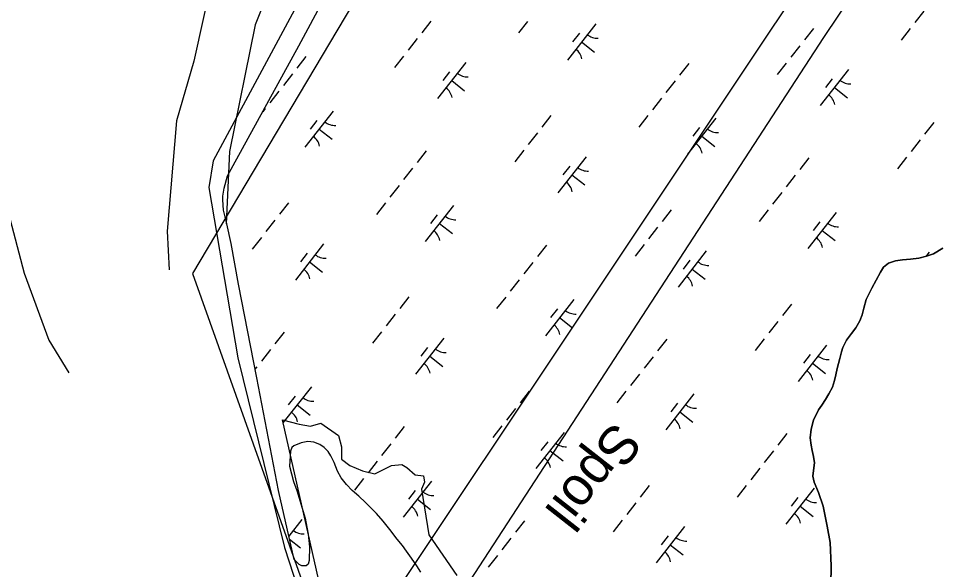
# Model space of a CAD drawing. Extents: x 3896831 to 3918110, y 171006 to 193349.
# Drawn here: x 3907802 to 3908805, y 177519 to 178119 of the extents above; entities that cross this region are included whole.
import ezdxf

# ---------------------------------------------------------------- set-up
doc = ezdxf.new("R2010")
doc.units = 0
for name, color, linetype in [('V-CHAN-SPOL', 7, 'Continuous'), ('V-RIVR-EDGE', 7, 'Continuous'), ('V-RRAP-FSHR', 7, 'Continuous'), ('V-TOPO-DPTH', 7, 'Continuous'), ('V-TOPO-MINR', 7, 'Continuous'), ('V-TOPO-SHOR', 7, 'Continuous'), ('V-UTIL-LINE', 7, 'Continuous'), ('V-WETL-SWMP', 7, 'Continuous')]:
    doc.layers.add(name, color=color, linetype=linetype)

msp = doc.modelspace()

# ---------------------------------------------------------------- linework, layer by layer
at = {"layer": 'V-RIVR-EDGE'}
for points in [[(3908140.8, 178198.6), (3908014.4, 177963.8), (3908009.9, 177934.5), (3908041.5, 177749.4), (3908092.3, 177542.9), (3908130.7, 177424.4)], [(3908136.3, 177476.3), (3908090.1, 177681.7), (3908108.1, 177677.2), (3908120.5, 177674.9), (3908131.8, 177678.3), (3908151, 177664.8), (3908154.4, 177652.3), (3908154.4, 177638.8), (3908163.4, 177632), (3908177, 177626.4), (3908190.5, 177623), (3908208.6, 177632), (3908219.8, 177633.2), (3908225.5, 177629.8), (3908234.5, 177621.9), (3908243.5, 177620.7), (3908244.7, 177614), (3908241.3, 177606.1), (3908249.2, 177556.4), (3908279.7, 177512.4)]]:
    msp.add_lwpolyline(points, dxfattribs=at)
at = {"layer": 'V-RRAP-FSHR'}
msp.add_lwpolyline([(3910095.3, 181395.6), (3909257.3, 180118.1), (3908889.4, 179541.5), (3908614.7, 178888.4), (3907991.9, 177840.9), (3908307, 176956.6)], dxfattribs=at)
at = {"layer": 'V-TOPO-DPTH'}
msp.add_lwpolyline([(3908187.5, 178582.2), (3908149.5, 178485.1), (3908118.7, 178425.4), (3908061.6, 178286.4), (3908015.2, 178171), (3907993.6, 178072.1), (3907974.6, 178007.1), (3907964.5, 177887.3), (3907966.5, 177845.1)], dxfattribs=at)
at = {"layer": 'V-TOPO-MINR'}
for points in [[(3908537.4, 179043.2), (3908434.2, 178833), (3908266.3, 178537.3), (3908184.5, 178417.7), (3908134.2, 178297.4), (3908060.4, 178111.6), (3908032.4, 177973.8), (3908028.6, 177895.2)], [(3907786.2, 178645.6), (3907752, 178569), (3907730.7, 178485.8), (3907721.7, 178357.1), (3907734.2, 178235.5), (3907783.8, 177937), (3907808.8, 177841.5), (3907835.6, 177768.6), (3907857.3, 177732.9)], [(3908187.5, 178582.2), (3908149.5, 178485.1), (3908118.7, 178425.4), (3908061.6, 178286.4), (3908015.2, 178171), (3907993.6, 178072.1), (3907974.6, 178007.1), (3907964.5, 177887.3), (3907966.5, 177845.1)]]:
    msp.add_lwpolyline(points, dxfattribs=at)
at = {"layer": 'V-TOPO-SHOR'}
for points in [[(3908744.3, 177847.9), (3908749.9, 177852.4), (3908757.3, 177854.8), (3908764.9, 177856), (3908773.8, 177856.5), (3908782.9, 177857.7), (3908791.1, 177859.8), (3908798.6, 177862.6), (3908809, 177868.5)], [(3908687, 177502.1), (3908687.2, 177522.8), (3908686.4, 177548.1), (3908683.1, 177565.9), (3908678.7, 177587.9), (3908673.5, 177602.6), (3908668.9, 177613.9), (3908667.2, 177620.3), (3908668, 177626.6), (3908669.1, 177634.8), (3908668.1, 177641.9), (3908666.5, 177648.5), (3908665.5, 177654.1), (3908664.6, 177662.1), (3908665.6, 177671.6), (3908668.2, 177681.5), (3908673.4, 177692.8), (3908677.1, 177697.7), (3908681.1, 177703.8), (3908684.7, 177710), (3908688.7, 177717.4), (3908691, 177724.7), (3908692.3, 177730.9), (3908693.8, 177737.7), (3908696.6, 177748.6), (3908698.5, 177755.6), (3908700.2, 177760.5), (3908704.2, 177768.5), (3908709.4, 177775.9), (3908714.1, 177781.9), (3908718.5, 177789.5), (3908721.1, 177796.2), (3908723, 177803.2), (3908725.6, 177812.7), (3908731.7, 177825.2), (3908740.9, 177842.6), (3908744.3, 177847.9)]]:
    msp.add_lwpolyline(points, dxfattribs=at)
at = {"layer": 'V-UTIL-LINE'}
for points in [[(3905549.4, 173652.6), (3906763.3, 174938.4), (3906949.5, 175133), (3906970.6, 175166.8), (3907325.9, 175860.5), (3907748.9, 176681), (3908142.2, 177273.2), (3908679.4, 178098), (3908869.7, 178381.4), (3908937.4, 178537.8), (3909170, 179117.3), (3909533.8, 179633.3), (3910092.1, 180424.3), (3910333.2, 180766.9), (3910760.4, 181291.4), (3910921.1, 181524), (3911225.6, 181951.2), (3911822, 182788.6), (3911961.6, 182987.4), (3912147.7, 183114.3), (3912722.9, 183841.8), (3913090.9, 184307.1), (3913848, 185258.8), (3914364, 185910.1)], [(3913133.2, 183520.4), (3913116.3, 183516.1), (3912989.4, 183516.1), (3912744.1, 183393.5), (3911902.4, 182441.8), (3910866.1, 181249.1), (3910603.9, 180953), (3910214.7, 180504.6), (3910138.6, 180390.4), (3909757.9, 179819.4), (3909457.6, 179366.9), (3909009.3, 178685.9), (3908785.1, 178351.7), (3908150.7, 177400.1), (3907770, 176816.4), (3907693.9, 176706.4), (3907647.3, 176630.3), (3907300.5, 175936.6), (3907025.6, 175369.8), (3906945.2, 175204.9), (3906416.5, 174650.8), (3905507.1, 173682.2)]]:
    msp.add_lwpolyline(points, dxfattribs=at)
at = {"layer": 'V-WETL-SWMP'}
for p, q in [((3908107.9, 178089), (3908150.2, 178168)), ((3908788.3, 178126.7), (3908778.4, 178114.1)), ((3908251.4, 178115.6), (3908241.5, 178103)), ((3908356.9, 178115.5), (3908347, 178102.9)), ((3908431, 178112.8), (3908400.1, 178073.4)), ((3908668, 178107.9), (3908658.2, 178095.3)), ((3908773.5, 178107.8), (3908763.6, 178095.2)), ((3908236.6, 178096.7), (3908226.7, 178084.1)), ((3908413.2, 178102.6), (3908405.8, 178093.1)), ((3908030.1, 177947.5), (3908107.9, 178089)), ((3908415.6, 178093.1), (3908429.7, 178082)), ((3908653.2, 178089), (3908643.4, 178076.4)), ((3908115.5, 178077.2), (3908105.7, 178064.7)), ((3908221.8, 178077.8), (3908211.9, 178065.2)), ((3908289.6, 178070.8), (3908258.8, 178031.5)), ((3908532.2, 178069.5), (3908522.3, 178057)), ((3908638.4, 178070.1), (3908628.6, 178057.5)), ((3908100.7, 178058.4), (3908090.9, 178045.8)), ((3908271.8, 178060.6), (3908264.4, 178051.2)), ((3908706.2, 178063.1), (3908675.4, 178023.8)), ((3908274.2, 178051.1), (3908288.3, 178040)), ((3908517.4, 178050.7), (3908507.5, 178038.1)), ((3908688.5, 178052.9), (3908681.1, 178043.5)), ((3908085.9, 178039.5), (3908076.1, 178026.9)), ((3908690.8, 178043.4), (3908705, 178032.3)), ((3908502.6, 178031.8), (3908492.7, 178019.2)), ((3908071.1, 178020.6), (3908068.4, 178017.1)), ((3908145.3, 178017.8), (3908114.4, 177978.5)), ((3908127.5, 178007.7), (3908120.1, 177998.2)), ((3908382.3, 178013), (3908372.4, 178000.4)), ((3908487.8, 178012.9), (3908477.9, 178000.3)), ((3908561.9, 178010.1), (3908531.1, 177970.8)), ((3908799, 178005.3), (3908789.1, 177992.7)), ((3908129.8, 177998.2), (3908144, 177987.1)), ((3908544.1, 178000), (3908536.7, 177990.5)), ((3908367.5, 177994.1), (3908357.6, 177981.5)), ((3908546.5, 177990.5), (3908560.7, 177979.4)), ((3908784.2, 177986.4), (3908774.3, 177973.8)), ((3908352.7, 177975.2), (3908342.8, 177962.6)), ((3908246.5, 177974.6), (3908236.6, 177962)), ((3908420.5, 177968.2), (3908389.7, 177928.8)), ((3908663.1, 177966.9), (3908653.2, 177954.3)), ((3908769.3, 177967.5), (3908759.5, 177954.9)), ((3908231.7, 177955.8), (3908221.8, 177943.2)), ((3908402.7, 177958), (3908395.3, 177948.6)), ((3908026.3, 177934.1), (3908030.1, 177947.5)), ((3908405.1, 177948.5), (3908419.3, 177937.4)), ((3908648.3, 177948.1), (3908638.4, 177935.5)), ((3908216.9, 177936.9), (3908207, 177924.3)), ((3908024.9, 177921.4), (3908025.1, 177925.4)), ((3908025.1, 177925.4), (3908026.3, 177934.1)), ((3908633.5, 177929.2), (3908623.6, 177916.6)), ((3908025.9, 177910.1), (3908024.9, 177921.4)), ((3908096.6, 177918.1), (3908086.7, 177905.5)), ((3908202.1, 177918), (3908192.2, 177905.4)), ((3908276.2, 177915.2), (3908245.3, 177875.9)), ((3908027.5, 177902.9), (3908025.9, 177910.1)), ((3908258.4, 177905), (3908251, 177895.6)), ((3908513.2, 177910.4), (3908503.4, 177897.8)), ((3908618.7, 177910.3), (3908608.8, 177897.7)), ((3908692.8, 177907.5), (3908662, 177868.2)), ((3908029.5, 177895.2), (3908027.5, 177902.9)), ((3908034.1, 177873.7), (3908029.5, 177895.2)), ((3908081.8, 177899.2), (3908071.9, 177886.6)), ((3908260.8, 177895.6), (3908274.9, 177884.5)), ((3908675, 177897.3), (3908667.6, 177887.9)), ((3908498.4, 177891.5), (3908488.6, 177878.9)), ((3908677.4, 177887.9), (3908691.6, 177876.8)), ((3908067, 177880.3), (3908057.1, 177867.7)), ((3908042.1, 177829.4), (3908034.1, 177873.7)), ((3908134.8, 177873.3), (3908104, 177833.9)), ((3908377.4, 177872), (3908367.5, 177859.4)), ((3908483.6, 177872.6), (3908473.8, 177860)), ((3908551.4, 177865.6), (3908520.6, 177826.2)), ((3908809, 177868.5), (3908798.6, 177862.6)), ((3908117, 177863.1), (3908109.6, 177853.6)), ((3908533.6, 177855.4), (3908526.2, 177845.9)), ((3908757.3, 177854.8), (3908749.9, 177852.4)), ((3908764.9, 177856), (3908757.3, 177854.8)), ((3908773.8, 177856.5), (3908764.9, 177856)), ((3908782.9, 177857.7), (3908773.8, 177856.5)), ((3908791.1, 177859.8), (3908782.9, 177857.7)), ((3908794, 177864.3), (3908790.4, 177859.6)), ((3908798.6, 177862.6), (3908791.1, 177859.8)), ((3908119.4, 177853.6), (3908133.5, 177842.5)), ((3908362.6, 177853.1), (3908352.7, 177840.5)), ((3908536, 177845.9), (3908550.2, 177834.8)), ((3908744.3, 177847.9), (3908740.9, 177842.6)), ((3908749.9, 177852.4), (3908744.3, 177847.9)), ((3908740.9, 177842.6), (3908731.7, 177825.2)), ((3908062.1, 177727.5), (3908042.1, 177829.4)), ((3908347.8, 177834.3), (3908337.9, 177821.7)), ((3908731.7, 177825.2), (3908725.6, 177812.7)), ((3908227.5, 177815.5), (3908217.6, 177802.9)), ((3908333, 177815.4), (3908323.1, 177802.8)), ((3908407.1, 177812.6), (3908376.3, 177773.3)), ((3908644.2, 177807.8), (3908634.3, 177795.2)), ((3908725.6, 177812.7), (3908723, 177803.2)), ((3908212.7, 177796.6), (3908202.8, 177784)), ((3908389.3, 177802.4), (3908381.9, 177793)), ((3908721.1, 177796.2), (3908718.5, 177789.5)), ((3908723, 177803.2), (3908721.1, 177796.2)), ((3908391.7, 177793), (3908405.9, 177781.8)), ((3908629.3, 177788.9), (3908619.5, 177776.3)), ((3908718.5, 177789.5), (3908714.1, 177781.9)), ((3908091.7, 177777.1), (3908081.8, 177764.5)), ((3908197.9, 177777.7), (3908188, 177765.1)), ((3908709.4, 177775.9), (3908704.2, 177768.5)), ((3908714.1, 177781.9), (3908709.4, 177775.9)), ((3908265.7, 177770.7), (3908234.9, 177731.3)), ((3908508.3, 177769.4), (3908498.4, 177756.8)), ((3908614.5, 177770), (3908604.7, 177757.4)), ((3908704.2, 177768.5), (3908700.2, 177760.5)), ((3908076.9, 177758.2), (3908067, 177745.6)), ((3908247.9, 177760.5), (3908240.5, 177751)), ((3908682.4, 177763), (3908651.5, 177723.6)), ((3908698.5, 177755.6), (3908696.6, 177748.6)), ((3908700.2, 177760.5), (3908698.5, 177755.6)), ((3908250.3, 177751), (3908264.5, 177739.9)), ((3908493.5, 177750.5), (3908483.6, 177737.9)), ((3908664.6, 177752.8), (3908657.2, 177743.3)), ((3908696.6, 177748.6), (3908693.8, 177737.7)), ((3908062.1, 177739.3), (3908060.3, 177737.1)), ((3908666.9, 177743.3), (3908681.1, 177732.2)), ((3908693.8, 177737.7), (3908692.3, 177730.9)), ((3908085.5, 177605), (3908062.1, 177727.5)), ((3908478.7, 177731.6), (3908468.8, 177719.1)), ((3908691, 177724.7), (3908688.7, 177717.4)), ((3908692.3, 177730.9), (3908691, 177724.7)), ((3908121.4, 177717.7), (3908090.5, 177678.4)), ((3908688.7, 177717.4), (3908684.7, 177710)), ((3908103.6, 177707.5), (3908096.2, 177698.1)), ((3908358.4, 177712.9), (3908348.6, 177700.3)), ((3908463.9, 177712.8), (3908454, 177700.2)), ((3908538, 177710), (3908507.2, 177670.7)), ((3908684.7, 177710), (3908681.1, 177703.8)), ((3908106, 177698), (3908120.1, 177686.9)), ((3908520.2, 177699.8), (3908512.8, 177690.4)), ((3908677.1, 177697.7), (3908673.4, 177692.8)), ((3908681.1, 177703.8), (3908677.1, 177697.7)), ((3908343.6, 177694), (3908333.8, 177681.4)), ((3908522.6, 177690.3), (3908536.8, 177679.2)), ((3908673.4, 177692.8), (3908668.2, 177681.5)), ((3908222.6, 177674.5), (3908212.7, 177661.9)), ((3908328.8, 177675.1), (3908318.9, 177662.5)), ((3908668.2, 177681.5), (3908665.6, 177671.6)), ((3908396.6, 177668.1), (3908365.8, 177628.7)), ((3908639.2, 177666.8), (3908629.4, 177654.2)), ((3908665.6, 177671.6), (3908664.6, 177662.1)), ((3908110.2, 177656.7), (3908102.3, 177653.5)), ((3908117.4, 177658), (3908110.2, 177656.7)), ((3908124.1, 177657.3), (3908117.4, 177658)), ((3908130.8, 177654.9), (3908124.1, 177657.3)), ((3908135.5, 177651.5), (3908130.8, 177654.9)), ((3908207.8, 177655.6), (3908197.9, 177643)), ((3908378.8, 177657.9), (3908371.4, 177648.4)), ((3908664.6, 177662.1), (3908665.5, 177654.1)), ((3908098.6, 177647.5), (3908097.5, 177631.4)), ((3908100.3, 177651.7), (3908098.6, 177647.5)), ((3908102.3, 177653.5), (3908100.3, 177651.7)), ((3908139.7, 177647.3), (3908135.5, 177651.5)), ((3908142.5, 177642.6), (3908139.7, 177647.3)), ((3908381.2, 177648.4), (3908395.4, 177637.3)), ((3908624.4, 177647.9), (3908614.5, 177635.3)), ((3908665.5, 177654.1), (3908666.5, 177648.5)), ((3908666.5, 177648.5), (3908668.1, 177641.9)), ((3908146.3, 177635.2), (3908142.5, 177642.6)), ((3908150, 177625.8), (3908146.3, 177635.2)), ((3908193, 177636.7), (3908183.1, 177624.1)), ((3908669.1, 177634.8), (3908668, 177626.6)), ((3908668.1, 177641.9), (3908669.1, 177634.8)), ((3908097.5, 177631.4), (3908101.8, 177614.8)), ((3908153.8, 177618.7), (3908150, 177625.8)), ((3908609.6, 177629), (3908599.7, 177616.4)), ((3908668, 177626.6), (3908667.2, 177620.3)), ((3908101.8, 177614.8), (3908105.6, 177604.9)), ((3908159.6, 177611.5), (3908153.8, 177618.7)), ((3908178.2, 177617.8), (3908168.3, 177605.3)), ((3908252.3, 177615.1), (3908221.5, 177575.8)), ((3908667.2, 177620.3), (3908668.9, 177613.9)), ((3908102.7, 177529.6), (3908085.5, 177605)), ((3908105.6, 177604.9), (3908114.5, 177574.8)), ((3908166, 177604.9), (3908159.6, 177611.5)), ((3908173, 177598.5), (3908166, 177604.9)), ((3908234.5, 177604.9), (3908227.1, 177595.5)), ((3908489.3, 177610.3), (3908479.5, 177597.7)), ((3908594.8, 177610.1), (3908584.9, 177597.6)), ((3908668.9, 177607.4), (3908638.1, 177568.1)), ((3908668.9, 177613.9), (3908673.5, 177602.6)), ((3908180.3, 177591.8), (3908173, 177598.5)), ((3908236.9, 177595.4), (3908251, 177584.3)), ((3908651.1, 177597.2), (3908643.7, 177587.8)), ((3908673.5, 177602.6), (3908678.7, 177587.9)), ((3908186.2, 177585.9), (3908180.3, 177591.8)), ((3908192.5, 177579.8), (3908186.2, 177585.9)), ((3908474.5, 177591.4), (3908464.7, 177578.8)), ((3908653.5, 177587.7), (3908667.7, 177576.6)), ((3908678.7, 177587.9), (3908683.1, 177565.9)), ((3908114.5, 177574.8), (3908118.1, 177557.2)), ((3908199.5, 177571.4), (3908192.5, 177579.8)), ((3908110.9, 177573.2), (3908096.8, 177555.2)), ((3908206.7, 177562.5), (3908199.5, 177571.4)), ((3908353.5, 177571.9), (3908343.6, 177559.3)), ((3908459.7, 177572.5), (3908449.9, 177559.9)), ((3908527.6, 177565.5), (3908496.7, 177526.1)), ((3908683.1, 177565.9), (3908686.4, 177548.1)), ((3908118.1, 177557.2), (3908119.2, 177543.6)), ((3908214.7, 177551.9), (3908206.7, 177562.5)), ((3908509.8, 177555.3), (3908502.4, 177545.8)), ((3908097.6, 177551.8), (3908109.7, 177542.4)), ((3908220.5, 177544.8), (3908214.7, 177551.9)), ((3908225, 177538.9), (3908220.5, 177544.8)), ((3908338.7, 177553), (3908328.8, 177540.4)), ((3908512.1, 177545.8), (3908526.3, 177534.7)), ((3908686.4, 177548.1), (3908687.2, 177522.8)), ((3908119.2, 177543.6), (3908119, 177528.7)), ((3908230.5, 177531.3), (3908225, 177538.9)), ((3908323.9, 177534.1), (3908314, 177521.5)), ((3908108.1, 177524.2), (3908102.7, 177529.6)), ((3908111.1, 177522.7), (3908108.1, 177524.2)), ((3908118.1, 177524.5), (3908115.6, 177522.8)), ((3908119, 177528.7), (3908118.1, 177524.5)), ((3908236.2, 177522.9), (3908230.5, 177531.3)), ((3908115.6, 177522.8), (3908111.1, 177522.7)), ((3908240.5, 177516), (3908236.2, 177522.9)), ((3908687.2, 177522.8), (3908687, 177502.1))]:
    msp.add_line(p, q, dxfattribs=at)
for centre, start, end in [((3908432.8, 178114.7), 231.1403, 272.6839), ((3908398.7, 178071.2), 11.1403, 52.6839), ((3908291.4, 178072.7), 231.1403, 272.6839), ((3908708, 178065), 231.1403, 272.6839), ((3908257.3, 178029.2), 11.1403, 52.6839), ((3908674, 178021.5), 11.1403, 52.6839), ((3908147.1, 178019.8), 231.1403, 272.6839), ((3908563.7, 178012.1), 231.1403, 272.6839), ((3908113, 177976.3), 11.1403, 52.6839), ((3908529.6, 177968.6), 11.1403, 52.6839), ((3908422.3, 177970.1), 231.1403, 272.6839), ((3908388.2, 177926.6), 11.1403, 52.6839), ((3908278, 177917.2), 231.1403, 272.6839), ((3908694.6, 177909.5), 231.1403, 272.6839), ((3908243.9, 177873.7), 11.1403, 52.6839), ((3908660.6, 177866), 11.1403, 52.6839), ((3908136.6, 177875.2), 231.1403, 272.6839), ((3908102.5, 177831.7), 11.1403, 52.6839), ((3908553.2, 177867.5), 231.1403, 272.6839), ((3908519.2, 177824), 11.1403, 52.6839), ((3908408.9, 177814.5), 231.1403, 272.6839), ((3908374.8, 177771.1), 11.1403, 52.6839), ((3908267.5, 177772.6), 231.1403, 272.6839), ((3908684.2, 177764.9), 231.1403, 272.6839), ((3908233.4, 177729.1), 11.1403, 52.6839), ((3908650.1, 177721.4), 11.1403, 52.6839), ((3908123.2, 177719.6), 231.1403, 272.6839), ((3908539.8, 177711.9), 231.1403, 272.6839), ((3908089.1, 177676.2), 11.1403, 52.6839), ((3908505.8, 177668.5), 11.1403, 52.6839), ((3908398.4, 177670), 231.1403, 272.6839), ((3908364.4, 177626.5), 11.1403, 52.6839), ((3908254.1, 177617), 231.1403, 272.6839), ((3908670.7, 177609.3), 231.1403, 272.6839), ((3908220, 177573.5), 11.1403, 52.6839), ((3908636.7, 177565.8), 11.1403, 52.6839), ((3908112.7, 177575.1), 231.1403, 272.6839), ((3908529.4, 177567.4), 231.1403, 272.6839), ((3908495.3, 177523.9), 11.1403, 52.6839)]:
    msp.add_arc(centre, 17.6, start, end, dxfattribs=at)

# ---------------------------------------------------------------- texts
at = {"layer": 'V-CHAN-SPOL'}
msp.add_text('Spoil', height=42, rotation=231.9086, dxfattribs=at).set_placement((3908450.9, 177681.7))

doc.saveas('drawing.dxf')
